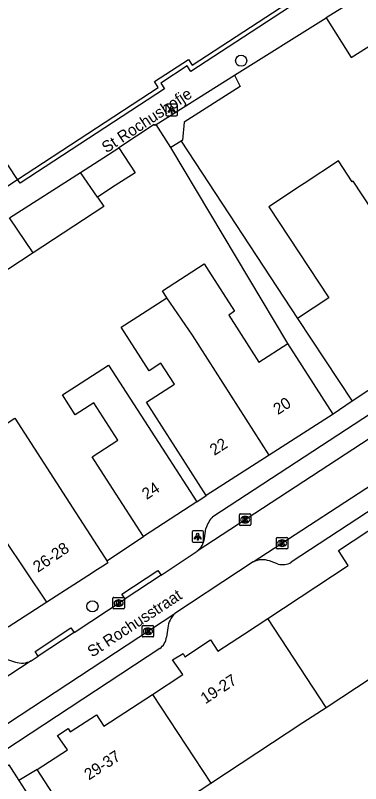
# Model space of a CAD drawing. Extents: x 161801 to 162379, y 382315 to 382832.
# Drawn here: x 162071.4 to 162101.6, y 382570.1 to 382637.3 of the extents above; entities that cross this region are included whole.
import ezdxf

# ---------------------------------------------------------------- set-up
doc = ezdxf.new("R2010")
doc.units = 0
for name, color, linetype in [('IMGEO_Boom', 7, 'Continuous'), ('IMGEO_Groenvoorziening', 7, 'Continuous'), ('IMGEO_Haag', 7, 'Continuous'), ('IMGEO_Kolk', 7, 'Continuous'), ('IMGEO_Lichtpunt', 7, 'Continuous'), ('IMGEO_Openbare_ruimte_label', 7, 'Continuous'), ('IMGEO_Pand', 7, 'Continuous'), ('IMGEO_Pand_nummerreeks', 7, 'Continuous'), ('IMGEO_Rijbaan_lokaal_open', 7, 'Continuous'), ('IMGEO_Voetpad_open', 7, 'Continuous')]:
    doc.layers.add(name, color=color, linetype=linetype)

msp = doc.modelspace()

# ---------------------------------------------------------------- linework, layer by layer
at = {"layer": 'IMGEO_Boom'}
for centre in [(162091.193, 382633.351), (162078.182, 382585.641)]:
    msp.add_circle(centre, 0.489, dxfattribs=at)
at = {"layer": 'IMGEO_Groenvoorziening'}
for points in [[(162090.621, 382632.077), (162091.121, 382631.109), (162086.211, 382627.989), (162086.065, 382626.396), (162085.935, 382626.314)], [(162085.049, 382625.755), (162083.747, 382627.769)]]:
    msp.add_lwpolyline(points, dxfattribs=at)
at = {"layer": 'IMGEO_Haag'}
msp.add_lwpolyline([(162071.632, 382622.978), (162083.938, 382631.006), (162083.617, 382631.522), (162086.587, 382633.461), (162086.912, 382632.968), (162098.453, 382640.526), (162100.721, 382642.321), (162107.093, 382646.349)], dxfattribs=at)
at = {"layer": 'IMGEO_Kolk'}
for p, q in [((162091.038, 382592.789), (162091.038, 382593.641)), ((162091.113, 382593.715), (162091.965, 382593.715)), ((162091.526, 382593.495), (162091.551, 382593.495)), ((162092.039, 382593.641), (162092.039, 382592.789)), ((162091.549, 382592.935), (162091.524, 382592.935)), ((162091.965, 382592.715), (162091.113, 382592.715)), ((162094.275, 382590.74), (162094.275, 382591.592)), ((162094.35, 382591.666), (162095.202, 382591.666)), ((162094.763, 382591.446), (162094.788, 382591.446)), ((162095.276, 382591.592), (162095.276, 382590.74)), ((162094.786, 382590.886), (162094.761, 382590.886)), ((162095.202, 382590.666), (162094.35, 382590.666)), ((162079.975, 382585.495), (162079.975, 382586.347)), ((162080.05, 382586.421), (162080.902, 382586.421)), ((162080.463, 382586.201), (162080.488, 382586.201)), ((162080.976, 382586.347), (162080.976, 382585.495)), ((162080.902, 382585.421), (162080.05, 382585.421)), ((162080.486, 382585.641), (162080.461, 382585.641)), ((162082.536, 382583.037), (162082.536, 382583.889)), ((162082.611, 382583.963), (162083.463, 382583.963)), ((162083.024, 382583.743), (162083.049, 382583.743)), ((162083.537, 382583.889), (162083.537, 382583.037)), ((162083.463, 382582.963), (162082.611, 382582.963)), ((162083.047, 382583.183), (162083.022, 382583.183))]:
    msp.add_line(p, q, dxfattribs=at)
for points in [[(162091.038, 382592.789), (162091.038, 382593.641)], [(162091.113, 382593.715), (162091.965, 382593.715)], [(162092.039, 382593.641), (162092.039, 382592.789)], [(162091.359, 382593.415), (162091.482, 382593.415), (162091.482, 382593.264), (162091.612, 382593.415), (162091.776, 382593.415), (162091.63, 382593.264), (162091.783, 382593.015), (162091.631, 382593.015), (162091.546, 382593.179), (162091.482, 382593.112), (162091.482, 382593.015), (162091.359, 382593.015), (162091.359, 382593.415)], [(162091.965, 382592.715), (162091.113, 382592.715)], [(162094.275, 382590.74), (162094.275, 382591.592)], [(162094.35, 382591.666), (162095.202, 382591.666)], [(162095.276, 382591.592), (162095.276, 382590.74)], [(162094.596, 382591.366), (162094.719, 382591.366), (162094.719, 382591.215), (162094.849, 382591.366), (162095.013, 382591.366), (162094.867, 382591.215), (162095.02, 382590.966), (162094.868, 382590.966), (162094.783, 382591.13), (162094.719, 382591.063), (162094.719, 382590.966), (162094.596, 382590.966), (162094.596, 382591.366)], [(162095.202, 382590.666), (162094.35, 382590.666)], [(162079.975, 382585.495), (162079.975, 382586.347)], [(162080.05, 382586.421), (162080.902, 382586.421)], [(162080.296, 382586.121), (162080.419, 382586.121), (162080.419, 382585.97), (162080.549, 382586.121), (162080.713, 382586.121), (162080.567, 382585.97), (162080.72, 382585.721), (162080.568, 382585.721), (162080.483, 382585.885), (162080.419, 382585.818), (162080.419, 382585.721), (162080.296, 382585.721), (162080.296, 382586.121)], [(162080.976, 382586.347), (162080.976, 382585.495)], [(162080.902, 382585.421), (162080.05, 382585.421)], [(162082.536, 382583.037), (162082.536, 382583.889)], [(162082.611, 382583.963), (162083.463, 382583.963)], [(162082.857, 382583.663), (162082.98, 382583.663), (162082.98, 382583.512), (162083.11, 382583.663), (162083.274, 382583.663), (162083.128, 382583.512), (162083.281, 382583.263), (162083.129, 382583.263), (162083.044, 382583.427), (162082.98, 382583.36), (162082.98, 382583.263), (162082.857, 382583.263), (162082.857, 382583.663)], [(162083.537, 382583.889), (162083.537, 382583.037)], [(162083.463, 382582.963), (162082.611, 382582.963)]]:
    msp.add_lwpolyline(points, dxfattribs=at)
for centre, start, end in [((162091.115, 382593.639), 91.55205, 178.44795), ((162091.115, 382593.639), 91.55205, 178.44795), ((162091.963, 382593.639), 1.55205, 88.44795), ((162091.963, 382593.639), 1.55205, 88.44795), ((162091.115, 382592.791), 181.55205, 268.44795), ((162091.115, 382592.791), 181.55205, 268.44795), ((162091.963, 382592.791), 271.55205, 358.44795), ((162091.963, 382592.791), 271.55205, 358.44795), ((162094.352, 382591.59), 91.55205, 178.44795), ((162094.352, 382591.59), 91.55205, 178.44795), ((162095.2, 382591.59), 1.55205, 88.44795), ((162095.2, 382591.59), 1.55205, 88.44795), ((162094.352, 382590.742), 181.55205, 268.44795), ((162094.352, 382590.742), 181.55205, 268.44795), ((162095.2, 382590.742), 271.55205, 358.44795), ((162095.2, 382590.742), 271.55205, 358.44795), ((162080.052, 382586.345), 91.55205, 178.44795), ((162080.052, 382586.345), 91.55205, 178.44795), ((162080.9, 382586.345), 1.55205, 88.44795), ((162080.9, 382586.345), 1.55205, 88.44795), ((162080.052, 382585.497), 181.55205, 268.44795), ((162080.052, 382585.497), 181.55205, 268.44795), ((162080.9, 382585.497), 271.55205, 358.44795), ((162080.9, 382585.497), 271.55205, 358.44795), ((162082.613, 382583.887), 91.55205, 178.44795), ((162082.613, 382583.887), 91.55205, 178.44795), ((162083.461, 382583.887), 1.55205, 88.44795), ((162083.461, 382583.887), 1.55205, 88.44795), ((162082.613, 382583.039), 181.55205, 268.44795), ((162082.613, 382583.039), 181.55205, 268.44795), ((162083.461, 382583.039), 271.55205, 358.44795), ((162083.461, 382583.039), 271.55205, 358.44795)]:
    msp.add_arc(centre, 0.0765, start, end, dxfattribs=at)
for centre, major_axis, ratio, start_param, end_param in [((162091.525, 382593.215), (-0.387, 0.002), 0.722429, 4.712389, 7.853982), ((162091.55, 382593.215), (-0.39, 0.002), 0.717154, 1.570796, 4.712389), ((162094.762, 382591.166), (-0.387, 0.002), 0.722429, 4.712389, 7.853982), ((162094.787, 382591.166), (-0.39, 0.002), 0.717154, 1.570796, 4.712389), ((162080.462, 382585.921), (-0.387, 0.002), 0.722429, 4.712389, 7.853982), ((162080.487, 382585.921), (-0.39, 0.002), 0.717154, 1.570796, 4.712389), ((162083.023, 382583.463), (-0.387, 0.002), 0.722429, 4.712389, 7.853982), ((162083.048, 382583.463), (-0.39, 0.002), 0.717154, 1.570796, 4.712389)]:
    msp.add_ellipse(centre, major_axis=major_axis, ratio=ratio, start_param=start_param, end_param=end_param, dxfattribs=at)
at = {"layer": 'IMGEO_Lichtpunt'}
for p, q in [((162084.617, 382629.448), (162084.617, 382628.641)), ((162084.617, 382629.448), (162084.617, 382628.641)), ((162085.519, 382629.543), (162084.711, 382629.543)), ((162085.519, 382629.543), (162084.711, 382629.543)), ((162085.613, 382628.641), (162085.613, 382629.448)), ((162085.613, 382628.641), (162085.613, 382629.448)), ((162084.711, 382628.547), (162085.519, 382628.547)), ((162084.711, 382628.547), (162085.519, 382628.547)), ((162086.896, 382592.144), (162086.896, 382591.337)), ((162086.896, 382592.144), (162086.896, 382591.337)), ((162087.798, 382592.239), (162086.99, 382592.239)), ((162087.798, 382592.239), (162086.99, 382592.239)), ((162087.892, 382591.337), (162087.892, 382592.144)), ((162087.892, 382591.337), (162087.892, 382592.144)), ((162086.99, 382591.243), (162087.798, 382591.243)), ((162086.99, 382591.243), (162087.798, 382591.243))]:
    msp.add_line(p, q, dxfattribs=at)
for points in [[(162084.991, 382629.112), (162085.03, 382629.084), (162084.842, 382628.822), (162084.804, 382628.849), (162084.991, 382629.112)], [(162085.093, 382629.064), (162085.14, 382629.064), (162085.14, 382628.742), (162085.093, 382628.742), (162085.093, 382629.064)], [(162085.203, 382629.084), (162085.241, 382629.111), (162085.428, 382628.849), (162085.389, 382628.821), (162085.203, 382629.084)], [(162087.27, 382591.808), (162087.309, 382591.78), (162087.121, 382591.518), (162087.083, 382591.545), (162087.27, 382591.808)], [(162087.372, 382591.76), (162087.419, 382591.76), (162087.419, 382591.438), (162087.372, 382591.438), (162087.372, 382591.76)], [(162087.482, 382591.78), (162087.52, 382591.807), (162087.707, 382591.545), (162087.668, 382591.517), (162087.482, 382591.78)]]:
    msp.add_lwpolyline(points, dxfattribs=at)
for centre in [(162085.116, 382629.246), (162087.395, 382591.942)]:
    msp.add_circle(centre, 0.0994, dxfattribs=at)
for centre, start, end in [((162084.711, 382629.448), 90, 180), ((162084.711, 382629.448), 90, 180), ((162085.519, 382629.448), 0, 90), ((162085.519, 382629.448), 0, 90), ((162084.711, 382628.641), 180, 270), ((162084.711, 382628.641), 180, 270), ((162085.519, 382628.641), 270, 0), ((162085.519, 382628.641), 270, 360), ((162086.99, 382592.144), 90, 180), ((162086.99, 382592.144), 90, 180), ((162087.798, 382592.144), 0, 90), ((162087.798, 382592.144), 0, 90), ((162086.99, 382591.337), 180, 270), ((162086.99, 382591.337), 180, 270), ((162087.798, 382591.337), 270, 0), ((162087.798, 382591.337), 270, 360)]:
    msp.add_arc(centre, 0.0946, start, end, dxfattribs=at)
at = {"layer": 'IMGEO_Pand'}
for points in [[(162101.503, 382638.903), (162098.642, 382637.101)], [(162098.642, 382637.101), (162100.825, 382633.634), (162104.377, 382635.872)], [(162077.142, 382623.583), (162078.763, 382624.621), (162080.497, 382625.732)], [(162080.497, 382625.732), (162081.918, 382623.562), (162080.183, 382622.426), (162078.638, 382621.414)], [(162107.295, 382618.041), (162105.098, 382616.595), (162100.999, 382622.82), (162100.9, 382622.755), (162099.695, 382624.586), (162096.703, 382622.616), (162096.461, 382622.456), (162093.624, 382620.587), (162098.869, 382612.622), (162096.136, 382610.823)], [(162070.936, 382619.608), (162077.142, 382623.583)], [(162078.638, 382621.414), (162077.142, 382623.583)], [(162078.638, 382621.414), (162079.171, 382620.6), (162072.987, 382616.551)], [(162072.987, 382616.551), (162070.936, 382619.608)], [(162072.987, 382616.551), (162067.591, 382613.018)], [(162084.704, 382612.618), (162084.305, 382613.231), (162087.96, 382615.577), (162088.355, 382614.962), (162090.613, 382611.444), (162090.101, 382611.115), (162092.75, 382606.986), (162095.284, 382608.613)], [(162088.137, 382595.338), (162085.454, 382599.519), (162084.251, 382601.393), (162082.905, 382603.49), (162085.355, 382605.063), (162084.177, 382606.898), (162083.143, 382606.234), (162080.697, 382610.046), (162081.731, 382610.71), (162084.704, 382612.618)], [(162093.646, 382598.873), (162086.924, 382609.345), (162084.704, 382612.618)], [(162112.221, 382611.038), (162100.902, 382603.585)], [(162096.136, 382610.823), (162100.902, 382603.585)], [(162099.233, 382602.459), (162096.533, 382606.667), (162095.284, 382608.613)], [(162082.652, 382591.76), (162079.935, 382595.957), (162078.151, 382598.714), (162080.418, 382600.181), (162078.303, 382603.447), (162076.676, 382602.394), (162075.555, 382604.126), (162077.182, 382605.179), (162079.574, 382606.727), (162084.597, 382598.965), (162087.309, 382594.774)], [(162065.036, 382606.054), (162065.992, 382604.57), (162068.712, 382600.348), (162071.402, 382602.082), (162076.727, 382593.822), (162079.228, 382589.942), (162079.436, 382589.619)], [(162074.18, 382585.997), (162070.512, 382591.487), (162068.266, 382594.971), (162066.2, 382598.307), (162063.19, 382602.79), (162062.232, 382604.321)], [(162099.233, 382602.459), (162093.646, 382598.873)], [(162093.646, 382598.873), (162088.137, 382595.338)], [(162087.309, 382594.774), (162082.652, 382591.76)], [(162093.517, 382584.575), (162100.557, 382589.214), (162099.697, 382590.512), (162104.937, 382593.957)], [(162079.436, 382589.619), (162079.543, 382589.454), (162079.316, 382589.308), (162078.387, 382588.709), (162078.179, 382588.575), (162074.18, 382585.997)], [(162083.431, 382577.945), (162086.082, 382579.685), (162085.201, 382580.956), (162086.106, 382581.529), (162086.276, 382581.23), (162088.523, 382582.702), (162089.165, 382581.708), (162091.498, 382583.245), (162093.517, 382584.575)], [(162098.622, 382576.803), (162093.517, 382584.575)], [(162098.622, 382576.803), (162102.649, 382579.449)], [(162073.335, 382571.365), (162075.996, 382573.093), (162075.118, 382574.348), (162076.07, 382574.953), (162076.231, 382574.669), (162078.539, 382576.155), (162079.193, 382575.162), (162083.431, 382577.945)], [(162083.431, 382577.945), (162088.533, 382570.177)], [(162088.533, 382570.177), (162096.601, 382575.476), (162098.622, 382576.803)], [(162065.531, 382568.448), (162068.617, 382570.478), (162068.686, 382570.371), (162070.867, 382571.77), (162071.745, 382570.4)], [(162078.441, 382563.548), (162076.088, 382567.15), (162073.335, 382571.365)], [(162071.745, 382570.4), (162073.566, 382567.561), (162077.668, 382561.162), (162078.029, 382560.599)], [(162078.441, 382563.548), (162088.533, 382570.177)]]:
    msp.add_lwpolyline(points, dxfattribs=at)
at = {"layer": 'IMGEO_Rijbaan_lokaal_open'}
for points in [[(162111.73, 382606.38), (162087.354, 382590.455)], [(162092.248, 382589.524), (162104.523, 382597.511)], [(162084.185, 382588.365), (162087.354, 382590.455)], [(162092.248, 382589.524), (162090.951, 382588.681), (162085.399, 382585.021)], [(162084.185, 382588.365), (162081.034, 382586.287)], [(162076.577, 382583.348), (162081.034, 382586.287)], [(162061.354, 382569.255), (162085.399, 382585.021)], [(162076.577, 382583.348), (162073.44, 382581.279)], [(162072.819, 382580.871), (162059.815, 382572.377)], [(162072.819, 382580.871), (162073.44, 382581.279)]]:
    msp.add_lwpolyline(points, dxfattribs=at)
at = {"layer": 'IMGEO_Voetpad_open'}
for points in [[(162107.093, 382646.349), (162107.365, 382646.048), (162100.953, 382641.994), (162098.687, 382640.201), (162086.798, 382632.415), (162086.472, 382632.908), (162084.164, 382631.401), (162084.484, 382630.885), (162071.854, 382622.645), (162071.632, 382622.978)], [(162090.621, 382632.077), (162098.642, 382637.101)], [(162083.747, 382627.769), (162090.621, 382632.077)], [(162071.632, 382622.978), (162066.874, 382630.15), (162061.847, 382626.837), (162066.568, 382619.672)], [(162083.747, 382627.769), (162083.638, 382627.701), (162083.591, 382627.773), (162080.497, 382625.732)], [(162085.935, 382626.314), (162085.049, 382625.755)], [(162095.284, 382608.613), (162085.049, 382625.755)], [(162085.935, 382626.314), (162096.136, 382610.823)], [(162066.568, 382619.672), (162071.632, 382622.978)], [(162088.725, 382593.485), (162108.41, 382606.351)], [(162100.902, 382603.585), (162099.233, 382602.459)], [(162087.309, 382594.774), (162088.137, 382595.338)], [(162103.003, 382594.362), (162095.567, 382589.499)], [(162087.982, 382591.578), (162088.094, 382592.454)], [(162079.436, 382589.619), (162082.652, 382591.76)], [(162094.438, 382589.33), (162093.663, 382589.606)], [(162081.034, 382586.287), (162080.761, 382586.705), (162083.912, 382588.784), (162084.185, 382588.365)], [(162074.18, 382585.997), (162070.796, 382583.816)], [(162073.44, 382581.279), (162073.167, 382581.697), (162076.304, 382583.766), (162076.577, 382583.348)], [(162084.771, 382583.747), (162084.659, 382582.935)], [(162084.078, 382581.943), (162069.384, 382572.306), (162069.129, 382572.673)], [(162070.752, 382581.005), (162071.439, 382580.767)], [(162073.335, 382571.365), (162071.745, 382570.4)]]:
    msp.add_lwpolyline(points, dxfattribs=at)
for centre, radius, start, end in [((162090.686, 382591.576), 2.737, 135.7729, 161.29157), ((162086.139, 382591.872), 1.867, 310.62453, 350.9462), ((162093.047, 382587.994), 1.726, 69.06902, 117.5642), ((162094.805, 382590.736), 1.453, 255.38047, 301.64631), ((162086.822, 382583.528), 2.063, 133.62047, 173.89887), ((162083.18, 382583.135), 1.492, 306.98331, 352.30291), ((162072.002, 382582.502), 1.824, 252.01247, 296.60713)]:
    msp.add_arc(centre, radius, start, end, dxfattribs=at)

# ---------------------------------------------------------------- texts
at = {"layer": 'IMGEO_Openbare_ruimte_label'}
for s, rotation, p in [('St Rochushofje', 33.21354, (162079.406, 382625.24)), ('St Rochusstraat', 33.24494, (162078.156, 382581.149))]:
    msp.add_text(s, height=1, rotation=rotation, dxfattribs=at).set_placement(p)
at = {"layer": 'IMGEO_Pand_nummerreeks'}
for s, rotation, p in [('20', 32.69297, (162094.406, 382602.354)), ('22', 32.69297, (162088.853, 382598.791)), ('24', 32.9107, (162082.918, 382594.933)), ('26-28', 34.21704, (162073.414, 382588.565)), ('19-27', 33.32216, (162088.058, 382577.061)), ('29-37', 33.09194, (162077.874, 382570.408))]:
    msp.add_text(s, height=1, rotation=rotation, dxfattribs=at).set_placement(p)

doc.saveas('drawing.dxf')
